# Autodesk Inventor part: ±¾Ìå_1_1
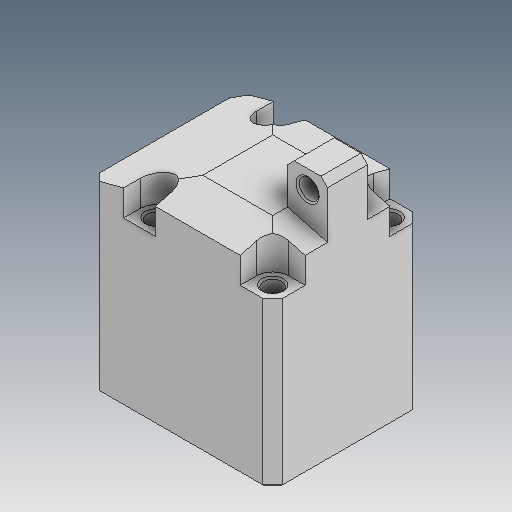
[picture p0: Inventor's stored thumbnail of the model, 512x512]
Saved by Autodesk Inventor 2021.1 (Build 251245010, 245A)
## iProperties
Created: 2019-04
Part Number: ±¾Ìå_1_1
Material: Ogólny
Document SubType Name: Modeling
Designer: user
Density: 1 g/cm^3
Appearance: Domyślna
Author: user
Revision Number: ÈÎºÎ
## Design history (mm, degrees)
feature "ÊäÈë1"
feature "ÊäÈë2"
node "Bryła1"
node "Bryła2"
